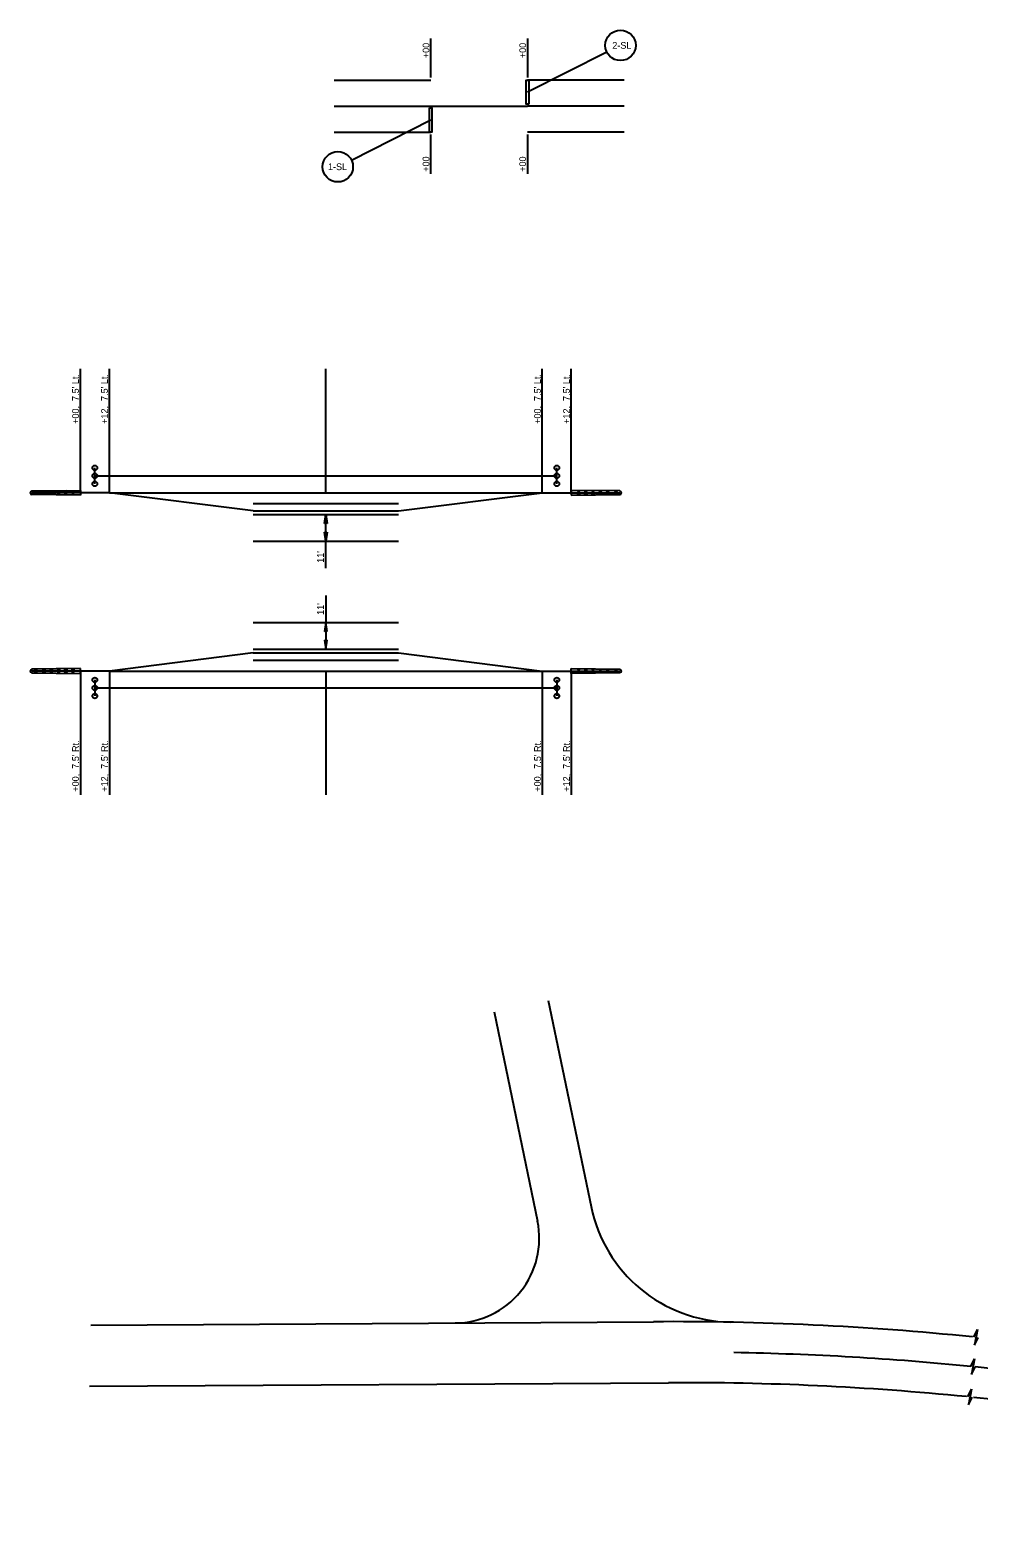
# Model space of a CAD drawing. Extents: x -1395 to 1843, y -1176 to 1887.
# Drawn here: x -806 to -414, y -308 to 316 of the extents above; entities that cross this region are included whole.
import ezdxf

# ---------------------------------------------------------------- set-up
doc = ezdxf.new("R2010")
doc.units = 0
for name, color, linetype in [('Default', 7, 'Continuous'), ('DR_P_Culvert', 7, 'Continuous'), ('DR_P_Ditch', 7, 'Continuous'), ('DR_X_Ditch', 7, 'Continuous'), ('SH_Major_Grid_Line', 7, 'Continuous'), ('SH_Named_Boundary', 7, 'Continuous'), ('XS_P_Headwall', 7, 'Continuous'), ('XS_P_Pavt_Layers', 7, 'Continuous'), ('XS_P_Pavt_Surface', 7, 'Continuous'), ('XS_X_Pavt', 7, 'Continuous')]:
    doc.layers.add(name, color=color, linetype=linetype)

msp = doc.modelspace()

# ---------------------------------------------------------------- linework, layer by layer
at = {"layer": 'Default'}
for start, end in [(84.29161, 89.02979), (70.97914, 84.20522)]:
    msp.add_arc((-535.28, -1418.74), 1187.6, start, end, dxfattribs=at)
at = {"layer": 'DR_P_Culvert'}
for centre in [(-779.45, 134.65), (-779.45, 131.32), (-588.4, 134.65), (-588.4, 131.32), (-779.45, 127.99), (-588.4, 127.99), (-779.45, 46.92), (-779.45, 43.6), (-588.4, 46.92), (-588.4, 43.6), (-779.45, 40.27), (-588.4, 40.27)]:
    msp.add_circle(centre, 1, dxfattribs=at)
at = {"layer": 'DR_P_Ditch'}
for points in [[(-600.02, 284.99), (-601.02, 284.99), (-601.02, 294.99), (-600.02, 294.99)], [(-641.02, 283.49), (-640.02, 283.49), (-640.02, 273.49), (-641.02, 273.49)]]:
    msp.add_lwpolyline(points, close=True, dxfattribs=at)
at = {"layer": 'DR_X_Ditch'}
for p, q in [((-591.92, -85.69), (-574.25, -170.91)), ((-614.36, -90.34), (-596.36, -176.91)), ((-781.14, -220), (-548.4, -218.51)), ((-781.63, -245.18), (-542.22, -243.76))]:
    msp.add_line(p, q, dxfattribs=at)
for centre, radius, start, end in [((-515.5, -158.73), 60, 191.71248, 268.88115), ((-630.63, -184.04), 35, 270.36504, 11.74476), ((-540.59, -1443.49), 1225, 84.1868, 90.36504), ((-535.28, -1418.74), 1175, 84.32081, 90.33829), ((-535.28, -1418.74), 1175, 70.97914, 84.17606)]:
    msp.add_arc(centre, radius, start, end, dxfattribs=at)
at = {"layer": 'SH_Major_Grid_Line'}
for centre in [(-562.06, 309.35), (-678.98, 259.14)]:
    msp.add_circle(centre, 6.29, dxfattribs=at)
at = {"layer": 'SH_Named_Boundary'}
for p, q in [((-640.52, 295.99), (-640.52, 312.24)), ((-600.52, 312.24), (-600.52, 295.99)), ((-680.52, 294.99), (-640.52, 294.99)), ((-560.52, 294.99), (-600.52, 294.99)), ((-560.52, 294.99), (-600.52, 294.99)), ((-680.52, 284.24), (-640.52, 284.24)), ((-640.52, 284.24), (-600.52, 284.24)), ((-560.52, 284.24), (-600.52, 284.24)), ((-680.52, 273.49), (-640.52, 273.49)), ((-680.52, 273.49), (-640.52, 273.49)), ((-640.52, 256.24), (-640.52, 272.49)), ((-560.52, 273.49), (-600.52, 273.49)), ((-600.52, 272.49), (-600.52, 256.24)), ((-779.45, 131.32), (-683.92, 131.32)), ((-683.92, 131.32), (-588.4, 131.32)), ((-785.45, 124.32), (-805.45, 124.32)), ((-773.45, 124.32), (-683.92, 124.32)), ((-683.92, 124.32), (-594.4, 124.32)), ((-582.4, 124.32), (-562.4, 124.32)), ((-713.92, 116.82), (-653.92, 116.82)), ((-713.92, 115.32), (-653.92, 115.32)), ((-713.92, 104.32), (-653.92, 104.32)), ((-713.92, 70.6), (-653.92, 70.6)), ((-713.92, 59.6), (-653.92, 59.6)), ((-713.92, 58.1), (-653.92, 58.1)), ((-785.45, 50.6), (-805.45, 50.6)), ((-773.45, 50.6), (-683.92, 50.6)), ((-683.92, 50.6), (-594.4, 50.6)), ((-582.4, 50.6), (-562.4, 50.6)), ((-779.45, 43.6), (-588.4, 43.6)), ((-415.93, -224.85), (-414.38, -221.69)), ((-414.38, -221.69), (-415.7, -228.19)), ((-415.7, -228.19), (-414.15, -225.03)), ((-417.16, -237.03), (-415.61, -233.87)), ((-415.61, -233.87), (-416.93, -240.37)), ((-416.93, -240.37), (-415.38, -237.21)), ((-418.42, -249.57), (-416.87, -246.41)), ((-416.87, -246.41), (-418.19, -252.91)), ((-418.19, -252.91), (-416.64, -249.75))]:
    msp.add_line(p, q, dxfattribs=at)
at = {"layer": 'XS_P_Headwall'}
for p, q in [((-773.45, 124.32), (-785.45, 124.32)), ((-713.92, 116.82), (-773.45, 124.32)), ((-653.92, 116.82), (-594.4, 124.32)), ((-594.4, 124.32), (-582.4, 124.32)), ((-713.92, 116.82), (-653.92, 116.82)), ((-713.92, 58.1), (-773.45, 50.6)), ((-713.92, 58.1), (-653.92, 58.1)), ((-653.92, 58.1), (-594.4, 50.6)), ((-773.45, 50.6), (-785.45, 50.6)), ((-594.4, 50.6), (-582.4, 50.6))]:
    msp.add_line(p, q, dxfattribs=at)
at = {"layer": 'XS_P_Pavt_Layers'}
for p, q in [((-713.92, 119.82), (-653.92, 119.82)), ((-713.92, 55.1), (-653.92, 55.1))]:
    msp.add_line(p, q, dxfattribs=at)
at = {"layer": 'XS_P_Pavt_Surface'}
for p, q in [((-567.71, 306.57), (-600.52, 289.99)), ((-673.33, 261.91), (-640.52, 278.49)), ((-785.45, 124.32), (-785.45, 175.52)), ((-773.45, 124.32), (-773.45, 175.52)), ((-683.92, 124.32), (-683.92, 175.52)), ((-594.4, 124.32), (-594.4, 175.52)), ((-582.4, 124.32), (-582.4, 175.52)), ((-779.45, 127.99), (-779.45, 134.65)), ((-588.4, 127.99), (-588.4, 134.65)), ((-684.54, 111.62), (-683.92, 115.32)), ((-683.92, 104.32), (-683.92, 115.32)), ((-683.92, 115.32), (-683.31, 111.61)), ((-684.54, 111.62), (-684.54, 111.62)), ((-683.92, 104.32), (-684.54, 108.03)), ((-684.54, 108.03), (-684.54, 108.02)), ((-683.31, 108.01), (-683.92, 104.32)), ((-683.31, 111.61), (-683.31, 111.61)), ((-683.31, 108.01), (-683.31, 108.01)), ((-683.92, 93.08), (-683.92, 104.32)), ((-683.92, 81.84), (-683.92, 70.6)), ((-683.92, 70.6), (-684.54, 66.89)), ((-683.92, 70.6), (-683.92, 59.6)), ((-683.31, 66.9), (-683.92, 70.6)), ((-684.54, 66.89), (-684.54, 66.89)), ((-684.54, 63.29), (-684.54, 63.29)), ((-684.54, 63.29), (-683.92, 59.6)), ((-683.92, 59.6), (-683.31, 63.31)), ((-683.31, 66.9), (-683.31, 66.9)), ((-683.31, 63.31), (-683.31, 63.3)), ((-785.45, 50.6), (-785.45, -0.61)), ((-773.45, 50.6), (-773.45, -0.61)), ((-683.92, 50.6), (-683.92, -0.61)), ((-594.4, 50.6), (-594.4, -0.61)), ((-582.4, 50.6), (-582.4, -0.61)), ((-779.45, 46.92), (-779.45, 40.27)), ((-588.4, 46.92), (-588.4, 40.27))]:
    msp.add_line(p, q, dxfattribs=at)
for centre, start, end in [((-683.93, 110.67), 56.17801, 122.85878), ((-683.92, 108.96), 236.17801, 302.85878), ((-683.92, 65.95), 57.14122, 123.82199), ((-683.93, 64.24), 237.14122, 303.82199)]:
    msp.add_arc(centre, 1.13, start, end, dxfattribs=at)
at = {"layer": 'XS_X_Pavt'}
for p, q in [((-805.45, 125.07), (-785.45, 125.32)), ((-803.45, 125.09), (-804.45, 123.55)), ((-803.45, 123.54), (-804.45, 125.08)), ((-803.95, 125.09), (-803.95, 123.55)), ((-799.95, 125.14), (-800.95, 123.51)), ((-799.95, 123.5), (-800.95, 125.12)), ((-800.45, 125.13), (-800.45, 123.5)), ((-796.95, 125.17), (-797.95, 123.47)), ((-796.95, 123.46), (-797.95, 125.16)), ((-797.45, 125.17), (-797.45, 123.47)), ((-793.95, 125.21), (-794.95, 123.44)), ((-793.95, 123.42), (-794.95, 125.2)), ((-794.45, 125.2), (-794.45, 123.43)), ((-790.95, 125.25), (-791.95, 123.4)), ((-790.95, 123.39), (-791.95, 125.24)), ((-791.45, 125.24), (-791.45, 123.39)), ((-787.95, 125.29), (-788.95, 123.36)), ((-787.95, 123.35), (-788.95, 125.27)), ((-788.45, 125.28), (-788.45, 123.35)), ((-785.45, 125.32), (-785.45, 123.32)), ((-582.4, 125.32), (-582.4, 123.32)), ((-562.4, 125.07), (-582.4, 125.32)), ((-579.9, 125.29), (-578.9, 123.36)), ((-579.9, 123.35), (-578.9, 125.27)), ((-579.4, 125.28), (-579.4, 123.35)), ((-576.9, 125.25), (-575.9, 123.4)), ((-576.9, 123.39), (-575.9, 125.24)), ((-576.4, 125.24), (-576.4, 123.39)), ((-573.9, 125.21), (-572.9, 123.44)), ((-573.9, 123.42), (-572.9, 125.2)), ((-573.4, 125.2), (-573.4, 123.43)), ((-570.9, 125.17), (-569.9, 123.47)), ((-570.9, 123.46), (-569.9, 125.16)), ((-570.4, 125.17), (-570.4, 123.47)), ((-567.9, 125.14), (-566.9, 123.51)), ((-567.9, 123.5), (-566.9, 125.12)), ((-567.4, 125.13), (-567.4, 123.5)), ((-564.4, 125.09), (-563.4, 123.55)), ((-564.4, 123.54), (-563.4, 125.08)), ((-563.9, 125.09), (-563.9, 123.55)), ((-785.45, 123.32), (-805.45, 123.57)), ((-582.4, 123.32), (-562.4, 123.57)), ((-785.45, 51.6), (-805.45, 51.35)), ((-803.45, 51.37), (-804.45, 49.83)), ((-803.45, 49.82), (-804.45, 51.36)), ((-803.95, 49.83), (-803.95, 51.36)), ((-799.95, 51.41), (-800.95, 49.79)), ((-799.95, 49.78), (-800.95, 51.4)), ((-800.45, 49.78), (-800.45, 51.41)), ((-796.95, 51.45), (-797.95, 49.75)), ((-796.95, 49.74), (-797.95, 51.44)), ((-797.45, 49.75), (-797.45, 51.45)), ((-793.95, 51.49), (-794.95, 49.71)), ((-793.95, 49.7), (-794.95, 51.48)), ((-794.45, 49.71), (-794.45, 51.48)), ((-790.95, 51.53), (-791.95, 49.68)), ((-790.95, 49.66), (-791.95, 51.51)), ((-791.45, 49.67), (-791.45, 51.52)), ((-787.95, 51.56), (-788.95, 49.64)), ((-787.95, 49.63), (-788.95, 51.55)), ((-788.45, 49.63), (-788.45, 51.56)), ((-785.45, 49.6), (-785.45, 51.6)), ((-582.4, 49.6), (-582.4, 51.6)), ((-582.4, 51.6), (-562.4, 51.35)), ((-579.9, 51.56), (-578.9, 49.64)), ((-579.9, 49.63), (-578.9, 51.55)), ((-579.4, 49.63), (-579.4, 51.56)), ((-576.9, 51.53), (-575.9, 49.68)), ((-576.9, 49.66), (-575.9, 51.51)), ((-576.4, 49.67), (-576.4, 51.52)), ((-573.9, 51.49), (-572.9, 49.71)), ((-573.9, 49.7), (-572.9, 51.48)), ((-573.4, 49.71), (-573.4, 51.48)), ((-570.9, 51.45), (-569.9, 49.75)), ((-570.9, 49.74), (-569.9, 51.44)), ((-570.4, 49.75), (-570.4, 51.45)), ((-567.9, 51.41), (-566.9, 49.79)), ((-567.9, 49.78), (-566.9, 51.4)), ((-567.4, 49.78), (-567.4, 51.41)), ((-564.4, 51.37), (-563.4, 49.83)), ((-564.4, 49.82), (-563.4, 51.36)), ((-563.9, 49.83), (-563.9, 51.36)), ((-805.45, 49.85), (-785.45, 49.6)), ((-562.4, 49.85), (-582.4, 49.6))]:
    msp.add_line(p, q, dxfattribs=at)
for centre, start, end in [((-805.45, 124.32), 90.00022, 270.00022), ((-562.4, 124.32), 269.99978, 89.99978), ((-805.45, 50.6), 89.99978, 269.99978), ((-562.4, 50.6), 270.00022, 90.00022)]:
    msp.add_arc(centre, 0.75, start, end, dxfattribs=at)

# ---------------------------------------------------------------- texts
at = {"layer": 'SH_Named_Boundary'}
for s, rotation, p in [('+00', 90.05606, (-641.11, 304.05)), ('+00', 90.05606, (-601.11, 304.05)), ('2-SL', 0.05606, (-565.45, 307.94)), ('+00', 90.05606, (-641.11, 257.07)), ('+00', 90.05606, (-601.11, 257.07)), ('1-SL', 0.05606, (-683.03, 257.74)), ("+00,  7.5' Lt.", 90.05606, (-786.03, 152.81)), ("+12,  7.5' Lt.", 90.05606, (-774.03, 152.81)), ("+00,  7.5' Lt.", 90.05606, (-594.97, 152.81)), ("+12,  7.5' Lt.", 90.05606, (-582.97, 152.81)), ("11'", 90.05606, (-684.74, 95.35)), ("11'", 89.94394, (-684.74, 73.82)), ("+00,  7.5' Rt.", 89.94394, (-786.05, 0.7)), ("+12,  7.5' Rt.", 89.94394, (-774.05, 0.7)), ("+00,  7.5' Rt.", 89.94394, (-594.99, 0.7)), ("+12,  7.5' Rt.", 89.94394, (-582.99, 0.7))]:
    msp.add_text(s, height=2.8, rotation=rotation, dxfattribs=at).set_placement(p)

doc.saveas('drawing.dxf')
